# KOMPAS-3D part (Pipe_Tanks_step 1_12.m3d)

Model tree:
1. X Axis
2. Y Axis
3. Z Axis  (labels: T-Bend Dn 50; Pipe Dn 50; Bend 90 Dn 50; C:\Program Files\ASCON\KOMPAS-3D V10\Sys\graphic.lyt)
     Òîëùèíà ñòåíêè 1 = 1

Referenced files in C:\Documents and Settings\kashirsky\Мои документы\Camtasia Studio\Pipelines3D\Tanks\: Tanks_step 1.a3d, Tanks_step 1.spw
Referenced files in C:\Documents and Settings\kashirsky\Мои документы\Camtasia Studio\Pipelines3D\Tanks\Tanks_step 1_Pipes\: Pipe_Tanks_step 1_12.m3d
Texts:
  Pipe Dn 50
  Steel ASTM A295
  Three Point Plane
  Plane at Angle
  Line and Point Plane
  Axis through Two Vertices
  Axis of Feature
  Axis of Conical Surface
  Axis through Edge
  Trim by Surface
  Trim by Sketch
  Feature with No History
  Intersection Axis of Two Planes
  Two Line Plane
  Line and Face Plane
  Bend by line
  Hole in sheet body
  Cut in sheet body
  Point in CM
  Linear Dimension from Line to Point
  Surface Finish Symbol
  Geometric Tolerance Symbol
  Leader #1
  Leader #2
  Leader #3
  Shape Deviations and Datum
  Node point number
  Mark of coordination axis
  Node point designation
  Mark/Reference designation with leader
  Mark/reference designation on line
  Mark/Reference designation without leader
  T-Bend Dn 50
  Bend 90 Dn 50
  Plane of section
